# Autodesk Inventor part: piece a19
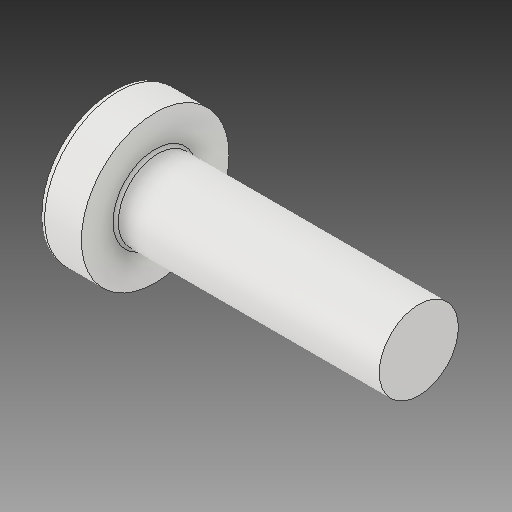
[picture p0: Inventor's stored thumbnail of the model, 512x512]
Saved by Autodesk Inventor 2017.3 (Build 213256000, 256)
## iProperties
Created: 1999-08
Part Number: piece a19
Material: solidworks materials|Alliage 7079|22
Document SubType Name: Modeling
Designer: ficho
Appearance: 255,255,255
Author: ficho
Sending System: SolidWorks 2009
Last Author: christophe
Last Saved: 2011-01-17
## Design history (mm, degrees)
feature "RecessCore"
node "Solide1"
